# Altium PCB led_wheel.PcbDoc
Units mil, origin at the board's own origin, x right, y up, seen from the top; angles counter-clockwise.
Board outline 3690 x 4845 mil, 2 copper layers (Top Layer, Bottom Layer); 32 components, 67 nets, 194 pads, 50 vias.
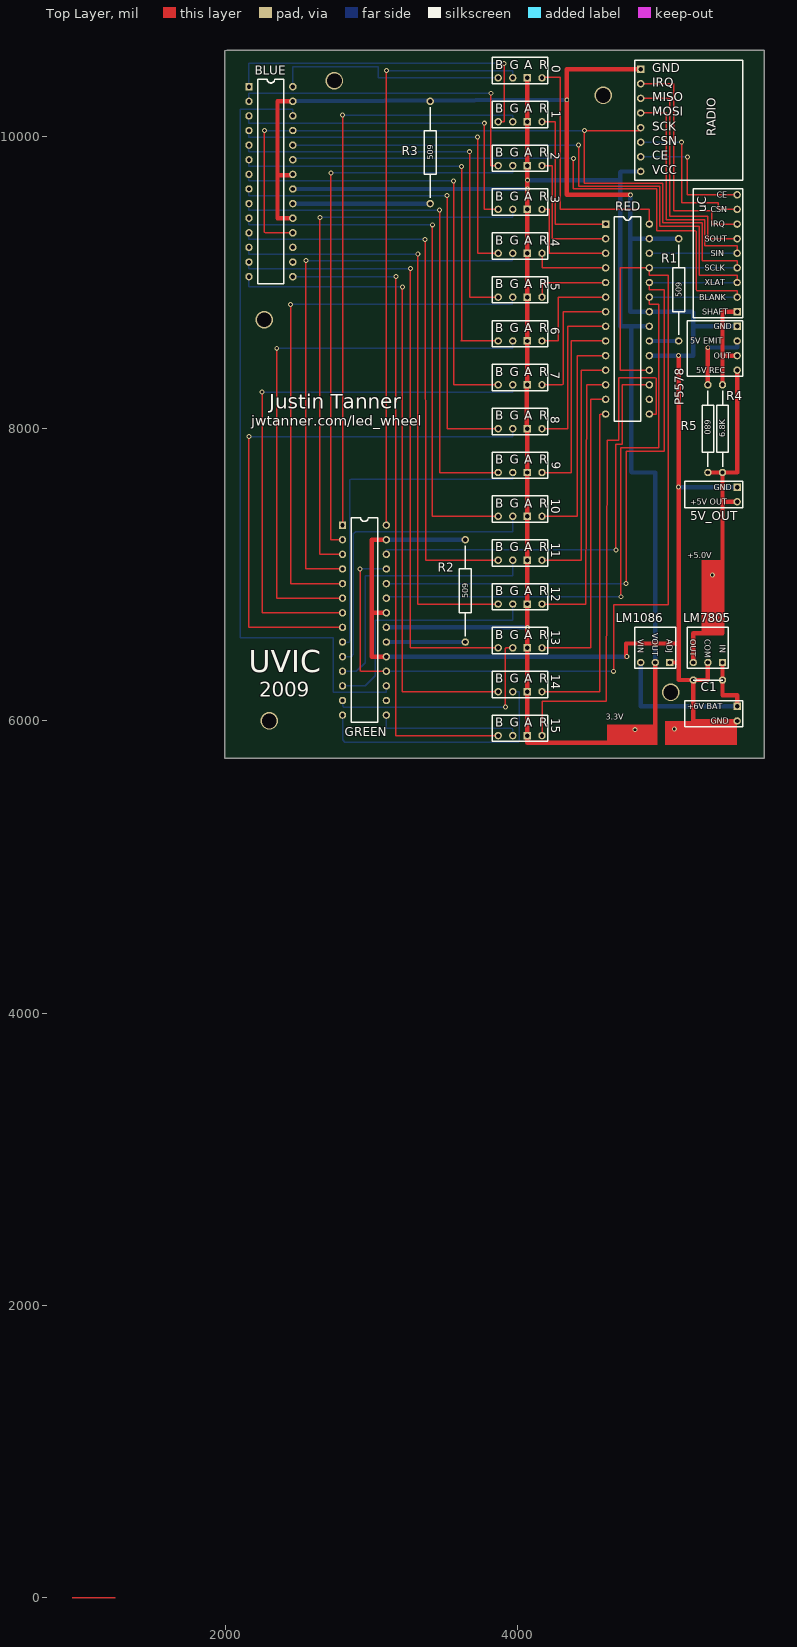
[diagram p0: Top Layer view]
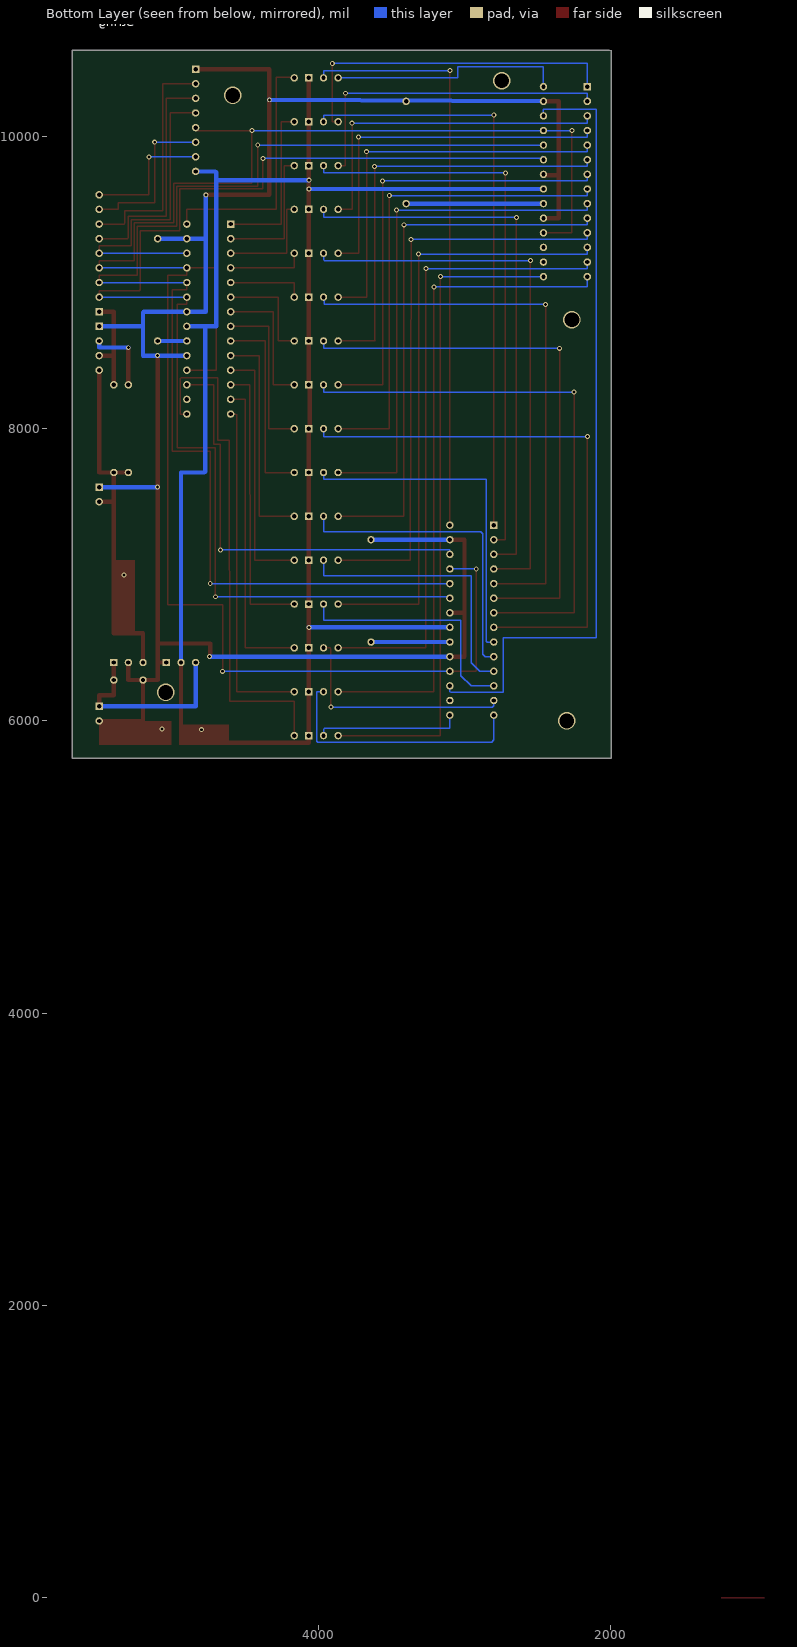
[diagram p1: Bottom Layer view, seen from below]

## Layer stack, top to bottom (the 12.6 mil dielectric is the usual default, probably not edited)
Top Layer: signal copper 1.4
Dielectric: dielectric 12.6, FR-4, Dk 4.8
Bottom Layer: signal copper 1.4

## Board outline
2010,10590 5685,10590 5685,5745 1995,5745 1995,10585

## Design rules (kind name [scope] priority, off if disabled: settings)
Clearance [All] p1: gap=7
ComponentClearance [All] p1: gap=10 collisioncheckmode=0
HoleSize [All] p1: absolutevalues=TRUE maxlimit=100 minlimit=15 maxpercent=80.000 minpercent=20.000
PolygonConnect [All] p1: connectstyle=Relief reliefconductorwidth=10 reliefentries=4 polygonreliefangle="90 Angle"
RoomDefinition led_wheel [InComponentClass('led_wheel')] p1: confinementstyle=ConfineIn formatcopy=TRUE outline 0,0 2000,0 2000,1000 0,1000
RoutingLayers [All] p1: top layer=Horizontal bottom layer=Vertical
RoutingVias [All] p1: holewidth=28 width=50 viastyle="Through Hole" minholewidth=28 minwidth=50 maxholewidth=28 maxwidth=50
SolderMaskExpansion [All] p1: expansion=4
TestPointUsage [All] p1: valid=0 allowmultiple=FALSE
Testpoint [All] p1: side=15 testpointundercomponent=TRUE minsize=40 maxsize=100 preferedsize=60 minholesize=0 maxholesize=40 preferedholesize=32 testpointgrid=1 style=1023 order=1234567890
Width [All] p1: maxlimit=30 minlimit=7 preferedwidth=10 toplayer_prefwidth=30 bottomlayer_prefwidth=30 minimp=50.000000 maximp=50.000000 favimp=50.000000
15 further rules are at their usual default settings.

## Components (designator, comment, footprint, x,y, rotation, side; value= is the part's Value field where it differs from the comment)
0 "*" LED 3665,10600 r0 top
1 "*" LED 3665,10300 r0 top
2 "*" LED 3665,10000 r0 top
3 "*" LED 3665,9700 r0 top
4 "*" LED 3665,9400 r0 top
5 "*" LED 3665,9100 r0 top
5V_OUT "*" "+5V OUT" 5600,7700 r270 top
6 "*" LED 3665,8800 r0 top
6V_BATTERIES "*" "+6V BAT" 5600,6200 r270 top
7 "*" LED 3665,8500 r0 top
8 "*" LED 3665,8200 r0 top
9 "*" LED 3665,7900 r0 top
10 "*" LED 3665,7600 r0 top
11 "*" LED 3665,7300 r0 top
12 "*" LED 3665,7000 r0 top
13 "*" LED 3665,6700 r0 top
14 "*" LED 3665,6400 r0 top
15 "*" LED 3665,6100 r0 top
BLUE "*" PDIP28 2160,10340 r0 top
C1 "Cap Pol1" C10 5400,6280 r180 top
GREEN "*" PDIP28 2800,7340 r0 top
LM1086 "*" LM1086 5140,6300 r180 top
LM7805 "*" LM7805 5500,6300 r180 top
P5578 "*" SHAFT 5600,8800 r270 top
R1 "509" R509 5100,8600 r90 top
R2 "Res1" R509 3640,6540 r90 top
R3 "Res1" R509 3400,9540 r90 top
R4 "Res1" R6.8K 5400,7700 r90 top
R5 "" R680 5300,8300 r270 top
RADIO "*" RADIO 5340,9960 r0 top
RED "*" PDIP28 4600,9400 r0 top
uC "*" "TO AT90" 5500,9000 r0 top (schematic designator TO_AT90)

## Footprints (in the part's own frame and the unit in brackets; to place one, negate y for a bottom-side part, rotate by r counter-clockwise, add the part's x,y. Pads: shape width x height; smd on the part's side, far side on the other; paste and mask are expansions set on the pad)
"+5V OUT" [mil]
  rect 51x51 hole 30: 1(100,-100)
  round 51 hole 30: 2(200,-100)
  silkscreen extent 60,-460 240,-60
"+6V BAT" [mil]
  rect 51x51 hole 30: 1(100,-100)
  round 51 hole 30: 2(200,-100)
  silkscreen extent 60,-460 240,-60
C10 [mil]
  round 51 hole 30: 1(0,0) 2(200,0)
  silkscreen extent 0,0 200,0
LED [mil]
  round 51 hole 30: 1(200,-200) 2(300,-200) 4(500,-200)
  rect 51x51 hole 30: 3(400,-200)
  silkscreen extent 160,-240 540,-60
LM1086 [mil]
  rect 51x51 hole 30: 1(100,-100)
  round 51 hole 30: 2(200,-100) 3(300,-100)
  silkscreen extent 60,-340 340,-60
LM7805 [mil]
  rect 51x51 hole 30: 1(100,-100)
  round 51 hole 30: 2(200,-100) 3(300,-100)
  silkscreen extent 60,-340 340,-60
PDIP28 [mil]
  rect 51x51 hole 30: 1(0,0)
  round 51 hole 30: 2(0,-100) 3(0,-200) 4(0,-300) 5(0,-400) 6(0,-500) 7(0,-600) 8(0,-700) 9(0,-800) 10(0,-900) 11(0,-1000) 12(0,-1100) 13(0,-1200) 14(0,-1300) 15(300,-1300) 16(300,-1200) 17(300,-1100) 18(300,-1000) 19(300,-900) 20(300,-800) 21(300,-700) 22(300,-600) 23(300,-500) 24(300,-400) 25(300,-300) 26(300,-200) 27(300,-100) 28(300,0)
  silkscreen extent 60,-1350 240,50
R6.8K [mil]
  round 51 hole 30: 1(0,0) 2(600,0)
  silkscreen extent 40,-40 560,40
R509 [mil]
  round 51 hole 30: 1(0,0) 2(700,0)
  silkscreen extent 41,-40 660,40
R680 [mil]
  round 51 hole 30: 1(0,0) 2(600,0)
  silkscreen extent 40,-40 560,40
RADIO [mil]
  rect 51x51 hole 30: 1(-500,500)
  round 51 hole 30: 2(-500,400) 3(-500,300) 4(-500,200) 5(-500,100) 6(-500,0) 7(-500,-100) 8(-500,-200)
  silkscreen extent -540,-260 200,560
SHAFT [mil]
  rect 51x51 hole 30: 1(100,-100)
  round 51 hole 30: 2(200,-100) 3(300,-100) 4(400,-100)
  silkscreen extent 60,-440 440,-60
"TO AT90" [mil]
  rect 51x51 hole 30: 1(0,-200)
  round 51 hole 30: 2(0,-100) 3(0,0) 4(0,100) 5(0,200) 6(0,300) 7(0,400) 8(0,500) 9(0,600)
  silkscreen extent -300,-240 40,640

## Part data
0 1 2 3 4 5 6 7 8 9 10 11 12 13 14 15: library part LED
5V_OUT: library part 5V_OUT
6V_BATTERIES: library part 6V_BATTERIES
BLUE GREEN RED: library part TLC5940NT
C1: library part "Cap Pol2", "Polarized Capacitor (Axial)"
LM1086: library part LM1086
LM7805: library part LM7805
P5578: library part P5578
R1 R5: library part Res1, "Resistor"
R2 R3 R4: "Resistor"
RADIO: library part RADIO
uC: library part TO_AT90

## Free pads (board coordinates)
  round 34 hole 20: 0(4065,9640) 3(4770,9600)
  round 31 hole 20: 1(4335,10250)

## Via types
v1: diameter 34, hole 20, Top Layer to Bottom Layer, 44 vias
v2: diameter 120, hole 100, Top Layer to Bottom Layer, 5 vias
v3: diameter 31, hole 20, Top Layer to Bottom Layer, 1 vias

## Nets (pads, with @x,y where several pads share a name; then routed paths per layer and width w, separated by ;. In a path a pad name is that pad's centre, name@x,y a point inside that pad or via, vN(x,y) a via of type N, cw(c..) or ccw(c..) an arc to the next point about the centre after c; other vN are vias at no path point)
+3.3V: 0.3 1.3 2.3 3.3 4.3 5.3 6.3 7.3 8.3 9.3 10.3 11.3 12.3 13.3 14.3 15.3 BLUE.21 GREEN.21 LM1086.2 pad.0 RADIO.8 RED.21 | length 12701.2
  Top Layer w10: 8.3@4060,8005 8.3 ; 7.3@4060,8295 7.3
  Top Layer w30: 8.3@4060,8005 7.3@4060,8295 ; 8.3 10.3 4065,5850 4620,5850 ; 7.3 5.3 0.3 ; 4940,5865 LM1086.2
  Bottom Layer w10: 4775,7705 4780,7700
  Bottom Layer w30: BLUE.21 pad.0 ; GREEN.21 v1(4065,6640) ; v1(4065,9700) 4700,9700 ; 4700,9755 4700,8700 RED.21 ; 4705,9760 RADIO.8 ; 4775,7705 4775,8700 ; 4780,7700 4940,7700 LM1086.2
  other v1: 4800,5940
+5V: 5V_OUT.2 LM7805.3 P5578.4 R4.1 R5.2 | length 2500
  Top Layer w30: LM7805.3 5200,6600 5400,6600 5400,7500 ; R5.2 5500,7700 P5578.4 ; R4.1 5400,7500 ; 5V_OUT.2 5400,7500
  other v1: 5330,7000
+6V: 6V_BATTERIES.1 C1.1 LM1086.3 LM7805.1 | length 1365
  Top Layer w10: 5495,6175 5500,6175
  Top Layer w30: LM7805.1 5400,6175 5500,6175 6V_BATTERIES.1
  Bottom Layer w30: LM1086.3 4840,6100 6V_BATTERIES.1
BLANK: BLUE.23 GREEN.23 RED.23 uC.2 | length 8612.4
  Top Layer w10: v1(4380,9850) 4380,9640 4950,9640 4950,9355 5215,9355 5220,9350 5220,8950 5225,8945 5500,8945 uC.2 ; v1(4705,6850) 4705,7870 4965,7870 4965,8850 4900,8850 RED.23
  Bottom Layer w10: BLUE.23 2460,9865 2475,9850 v1(4380,9850) ; GREEN.23 3100,6855 3105,6850 v1(4705,6850) ; RED.23 uC.2
BLUE0: 0.1 BLUE.28 | length 1615
  Bottom Layer w10: BLUE.28 2460,10475 3045,10475 3045,10400 0.1
BLUE1: 1.1 BLUE.1 | length 2345
  Top Layer w10: 1.1 3905,10100 3905,10355 v1(3905,10500)
  Bottom Layer w10: BLUE.1 2160,10500 v1(3905,10500)
BLUE2: 2.1 BLUE.2 | length 2255
  Top Layer w10: v1(3815,10295) 3815,9800 2.1
  Bottom Layer w10: BLUE.2 2160,10295 v1(3815,10295)
BLUE3: 3.1 BLUE.3 | length 2345
  Top Layer w10: v1(3770,10090) 3770,9500 3.1
  Bottom Layer w10: BLUE.3 2160,10090 v1(3770,10090)
BLUE4: 4.1 BLUE.4 | length 2545
  Top Layer w10: v1(3725,9995) 3725,9200 4.1
  Bottom Layer w10: BLUE.4 2160,9995 v1(3725,9995)
BLUE5: 5.1 BLUE.5 | length 2745
  Top Layer w10: v1(3670,9895) 3670,8900 5.1
  Bottom Layer w10: BLUE.5 2160,9895 v1(3670,9895)
BLUE6: 6.1 BLUE.6 | length 2952.1
  Top Layer w10: v1(3615,9795) 3615,8605 3610,8600 6.1
  Bottom Layer w10: BLUE.6 2160,9795 v1(3615,9795)
BLUE7: 7.1 BLUE.7 | length 3145
  Top Layer w10: v1(3560,9695) 3560,8300 7.1
  Bottom Layer w10: BLUE.7 2160,9695 v1(3560,9695)
BLUE8: 8.1 BLUE.8 | length 3345
  Top Layer w10: v1(3515,9595) 3515,8000 8.1
  Bottom Layer w10: BLUE.8 2160,9595 2270,9595 v1(3515,9595)
BLUE9: 9.1 BLUE.9 | length 3545
  Top Layer w10: v1(3465,9495) 3465,7700 9.1
  Bottom Layer w10: BLUE.9 2160,9495 v1(3465,9495)
BLUE10: 10.1 BLUE.10 | length 3745
  Top Layer w10: v1(3415,9395) 3415,7400 10.1
  Bottom Layer w10: BLUE.10 2160,9395 v1(3415,9395)
BLUE11: 11.1 BLUE.11 | length 3940
  Top Layer w10: v1(3365,9295) 3370,7100 11.1
  Bottom Layer w10: BLUE.11 2160,9295 v1(3365,9295)
BLUE12: 12.1 BLUE.12 | length 4145
  Top Layer w10: v1(3315,9195) 3315,9015 3315,9010 3315,6800 12.1
  Bottom Layer w10: BLUE.12 2160,9195 v1(3315,9195)
BLUE13: 13.1 BLUE.13 | length 4345
  Top Layer w10: v1(3265,9095) 3265,6500 13.1
  Bottom Layer w10: BLUE.13 2160,9095 2270,9095 v1(3265,9095)
BLUE14: 14.1 BLUE.14 | length 4545
  Top Layer w10: v1(3210,8970) 3210,6200 14.1
  Bottom Layer w10: BLUE.14 2160,8970 v1(3210,8970)
BLUE15: 15.1 BLUE.15 | length 4545
  Top Layer w10: v1(3165,9040) 3165,5900 15.1
  Bottom Layer w10: BLUE.15 v1(3165,9040)
"BLUE SOUT": BLUE.26 GREEN.17 | length 5437.1
  Bottom Layer w10: BLUE.26 2460,10185 2100,10185 2100,6570 2735,6570 2735,6195 3095,6195 3100,6200 GREEN.17
GND: 5V_OUT.1 6V_BATTERIES.2 BLUE.19 BLUE.22 BLUE.27 C1.2 GREEN.19 GREEN.22 GREEN.27 LM1086.1 LM7805.2 P5578.1 pad.1 pad.3 R1.2 R2.2 R3.2 RADIO.1 RED.19 RED.22 RED.27 | length 14554.2
  Top Layer w10: BLUE.22@2455,9735 BLUE.22
  Top Layer w30: 2355,9735 BLUE.22@2455,9735 ; BLUE.19 2355,9440 2355,10240 BLUE.27 ; 3005,6740 GREEN.22 ; GREEN.19 3000,6440 3000,7240 GREEN.27 ; 4335,10460 pad.1 4335,9600 pad.3 ; 4340,10460 RADIO.1 ; v1@4740,6440 4740,6530 5100,6530 ; LM1086.1 5100,6400 ; v1(5100,8500) 5100,6280 5300,6280 LM7805.2 ; C1.2 5200,6000 6V_BATTERIES.2
  Bottom Layer w10: 5195,8800 5200,8795
  Bottom Layer w30: BLUE.27 pad.1 ; GREEN.19 v1(4745,6440) ; GREEN.27 R2.2 ; pad.3 4770,9300 ; RED.19 5200,8500 5200,8795 ; v1(5100,7600) 5V_OUT.1 ; R1.2 RED.27 4770,9300 ; 5195,8800 RED.22 4770,8800 4770,9300 ; 5200,8700 P5578.1
  other v1: 5070,5945
GREEN0: 0.2 GREEN.28 | length 4012.1
  Top Layer w10: GREEN.28 v1(3100,10450)
  Bottom Layer w10: v1(3100,10450) 3960,10450 3965,10445 0.2@3965,10410
GREEN1: 1.2 GREEN.1 | length 4012.1
  Top Layer w10: GREEN.1 v1(2800,10145)
  Bottom Layer w10: v1(2800,10145) 3960,10145 3965,10140 1.2
GREEN2: 2.2 GREEN.2 | length 3885
  Top Layer w10: v1(2720,9750) 2720,7290 2720,7240 GREEN.2
  Bottom Layer w10: v1(2720,9750) 3965,9750 2.2
GREEN3: 3.2 GREEN.3 | length 3835
  Top Layer w10: v1(2645,9445) 2645,7145 2645,7140 GREEN.3
  Bottom Layer w10: v1(2645,9445) 3965,9445 3.2
GREEN4: 4.2 GREEN.4 | length 3822.1
  Top Layer w10: v1(2550,9150) 2550,7045 2550,7040 GREEN.4
  Bottom Layer w10: v1(2550,9150) 3960,9150 3965,9155 4.2
GREEN5: 5.2 GREEN.5 | length 3825
  Top Layer w10: v1(2445,8850) 2445,6940 GREEN.5
  Bottom Layer w10: v1(2445,8850) 3960,8850 5.2@3960,8895
GREEN6: 6.2 GREEN.6 | length 3825
  Top Layer w10: v1(2350,8550) 2350,6885 2350,6840 GREEN.6
  Bottom Layer w10: v1(2350,8550) 3965,8550 6.2
GREEN7: 7.2 GREEN.7 | length 3825
  Top Layer w10: v1(2250,8250) 2250,6780 2250,6740 GREEN.7
  Bottom Layer w10: v1(2250,8250) 3965,8250 7.2
GREEN8: 8.2 GREEN.8 | length 3805
  Top Layer w10: v1(2160,7945) 2160,6640 GREEN.8
  Bottom Layer w10: v1(2160,7945) 3965,7945 8.2
GREEN9: 9.2 GREEN.9 | length 2319.1
  Bottom Layer w10: GREEN.9 2845,6540 2850,6545 2850,7650 2855,7655 3965,7655 9.2
GREEN10: 10.2 GREEN.10 | length 2107.4
  Bottom Layer w10: GREEN.10 2860,6440 2875,6455 2875,7280 2890,7295 3965,7295 10.2
GREEN11: 11.2 GREEN.11 | length 1889.9
  Bottom Layer w10: GREEN.11 2895,6340 2955,6400 2955,6995 3965,6995 11.2
GREEN12: 12.2 GREEN.12 | length 1684
  Bottom Layer w10: GREEN.12 2955,6240 3025,6310 3025,6690 3965,6690 12.2
GREEN13: 13.2 GREEN.13 | length 1606.2
  Top Layer w10: v1(3915,6095) 3915,6495 3920,6500 13.2
  Bottom Layer w10: GREEN.13 2800,6105 2810,6095 v1(3915,6095)
GREEN14: 14.2 GREEN.14 | length 1773.3
  Bottom Layer w10: GREEN.14 2800,5870 2815,5855 4005,5855 4010,5860 4010,6200 14.2
GREEN15: 15.2 GREEN.15 | length 1002.1
  Bottom Layer w10: GREEN.15 3100,5950 3110,5950 3960,5950 3965,5945 15.2
IREF1: R1.1 RED.20 | length 200
  Bottom Layer w30: RED.20 R1.1
IREF2: GREEN.20 R2.1 | length 540
  Bottom Layer w30: GREEN.20 R2.1
IREF3: BLUE.20 R3.1 | length 940
  Bottom Layer w30: BLUE.20 R3.1
NetP5578_2: P5578.2 R5.1 | length 500
  Top Layer w30: R5.1 v3(5300,8555)
  Bottom Layer w30: v3(5300,8555) 5500,8555 P5578.2
NetP5578_3: P5578.3 R4.2 uC.1 | length 700
  Top Layer w10: 5400,8800 5405,8800
  Top Layer w30: R4.2 5400,8800 ; 5400,8500 P5578.3 ; 5405,8800 uC.1
"RADIO CE": RADIO.7 uC.9 | length 920
  Top Layer w10: v1(5160,9860) 5160,9600 uC.9
  Bottom Layer w10: RADIO.7 v1(5160,9860)
"RADIO CSN": RADIO.6 uC.8 | length 1120
  Top Layer w10: v1(5120,9960) 5120,9545 5370,9545 5370,9500 uC.8
  Bottom Layer w10: RADIO.6 v1(5120,9960)
"RADIO IRQ": RADIO.2 uC.7 | length 1614.1
  Top Layer w10: RADIO.2 5065,10360 5065,9495 5070,9490 5325,9490 5325,9405 5330,9400 uC.7
RED0: 0.4 RED.28 | length 1735
  Top Layer w10: 0.4@4170,10405 4290,10405 4290,9500 4900,9500 RED.28
RED1: 1.4 RED.1 | length 1135
  Top Layer w10: 1.4 4255,10100 4255,9400 RED.1
RED2: 2.4 RED.2 | length 935
  Top Layer w10: 2.4 4235,9800 4235,9300 RED.2
RED3: 3.4 RED.3 | length 735
  Top Layer w10: 3.4 4215,9500 4215,9200 RED.3
RED4: 4.4 RED.4 | length 535
  Top Layer w10: 4.4 4165,9100 RED.4
RED5: 5.4 RED.5 | length 535
  Top Layer w10: 5.4 4165,9000 RED.5
RED6: 6.4 RED.6 | length 735
  Top Layer w10: 6.4 4275,8600 4275,8900 RED.6
RED7: 7.4 RED.7 | length 932.1
  Top Layer w10: 7.4 4305,8300 4310,8305 4310,8800 RED.7
RED8: 8.4 RED.8 | length 1130
  Top Layer w10: 8.4 4340,8000 4340,8700 RED.8@4595,8700
RED9: 9.4 RED.9 | length 1330
  Top Layer w10: 9.4 4365,7700 4365,8600 RED.9@4595,8600
RED10: 10.4 RED.10 | length 1535
  Top Layer w10: 10.4 4405,7400 4405,8500 RED.10
RED11: 11.4 RED.11 | length 1735
  Top Layer w10: 11.4 4435,7100 4435,8400 RED.11
RED12: 12.4 RED.12 | length 1930
  Top Layer w10: 12.4 4465,6800 4470,8300 RED.12
RED13: 13.4 RED.13 | length 2135
  Top Layer w10: 13.4 4500,6500 4500,8200 RED.13
RED14: 14.4 RED.14 | length 2335
  Top Layer w10: 14.4 4560,6200 4560,8100 ; 4565,8100 RED.14@4605,8100
RED15: 15.4 RED.15 | length 3517.1
  Top Layer w10: 15.4 4165,6135 4605,6135 4610,7920 4690,7920 4690,8350 4940,8350 4945,8345 4945,8100 RED.15
"RED SOUT": GREEN.26 RED.17 | length 2960
  Top Layer w10: v1(4670,7170) 4670,7895 4715,7895 4715,8300 RED.17
  Bottom Layer w10: GREEN.26 3100,7170 v1(4670,7170)
SIN: RADIO.4 RED.26 uC.5 | length 2220
  Top Layer w10: RADIO.4 5015,10160 5015,9430 5280,9430 5280,9250 5500,9250 uC.5
  Bottom Layer w10: RED.26 uC.5
SOUT: RADIO.3 uC.6 | length 1617.1
  Top Layer w10: RADIO.3 5040,10260 5040,9455 5300,9455 5300,9305 5305,9300 uC.6
"SPI CLOCK": BLUE.18 BLUE.25 GREEN.18 GREEN.25 RADIO.5 RED.18 RED.25 uC.4 | length 13047.1
  Top Layer w10: v1(2265,10040) 2265,9345 2270,9340 BLUE.18 ; 2920,6340 v1(2920,7040) ; 2925,6340 GREEN.18 ; v1(4655,6340) 4655,6795 5030,6795 5030,9050 4900,9050 RED.25 4700,9100 4700,8400 RED.18 ; RADIO.5 4840,10040 v1(4455,10040) 4455,9680 4990,9680 4990,9410 5260,9410 5260,9150 5500,9150 uC.4
  Bottom Layer w10: v1(2265,10040) v1(4455,10040) ; v1(2920,7040) GREEN.25 ; GREEN.18 v1(4655,6340) ; RED.25 uC.4
XLAT: BLUE.24 GREEN.24 RED.24 uC.3 | length 8640
  Top Layer w10: v1(4415,9940) 4415,9660 4970,9660 4970,9385 5240,9385 5240,9050 5500,9050 uC.3 ; v1(4740,6940) 4740,7845 5000,7845 5000,8950 4900,8950 RED.24
  Bottom Layer w10: BLUE.24 v1(4415,9940) ; GREEN.24 v1(4740,6940) ; RED.24 uC.3
pads on no net: BLUE.16 BLUE.17 GREEN.16 RED.16
copper on no net: | length 340
  Top Layer w10: 950,0 1245,0 1200,0
  other v2: 2300,6000 5045,6195 2265,8745 4585,10280 2745,10380

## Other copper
Top Layer:
  rectangle net +5V: 5255,6600 5400,7100
  rectangle net GND: 5005,5835 5500,6000
  rectangle net +3.3V: 4610,5835 4955,5975

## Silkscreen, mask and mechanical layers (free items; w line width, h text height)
Top Overlay:
  text "Justin Tanner" at 2300,8135 h100
  text "jwtanner.com/led_wheel" at 2175,8020 h70
  text "+5.0V" at 5160,7115 h40
  text "UVIC" at 2160,6335 h150
  text "2009" at 2230,6165 h100
  text "3.3V" at 4600,6010 h40
Bottom Overlay:
  text "String" at 5260,10755 h60
Mechanical 1:
  lines w7: 2050,5800 5600,5800 5600,10565 2050,10565 2050,5800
